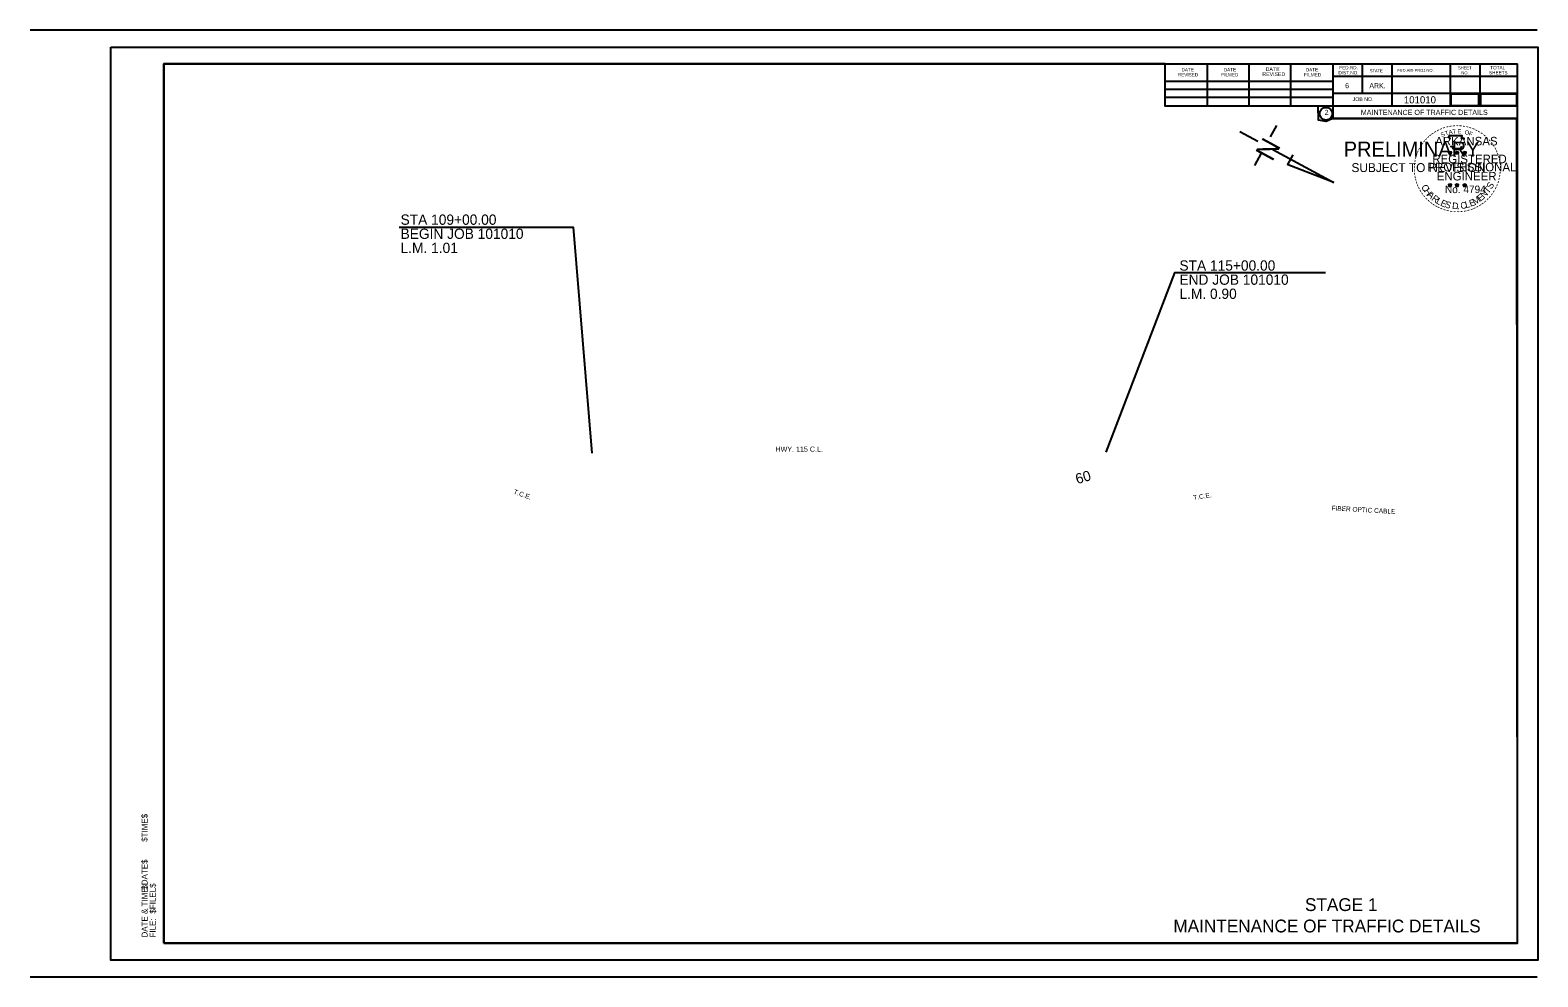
# Model space of a CAD drawing. Extents: x 6125 to 14104, y 8730 to 11067.
# Drawn here: x 9844 to 11605, y 9961 to 11067 of the extents above; entities that cross this region are included whole.
import ezdxf

# ---------------------------------------------------------------- set-up
doc = ezdxf.new("R2010")
doc.units = 0
for name, color, linetype in [('C-PSVP', 7, 'Continuous'), ('GREEN_TXT', 7, 'Continuous'), ('R_Border Notes', 7, 'Continuous'), ('R_MOT Stage 2', 7, 'Continuous'), ('R_Proposed Road', 7, 'Continuous'), ('R_Temp Const Easement Annot', 7, 'Continuous'), ('S_FIBER_OPTIC_CABLE_ANNOT', 7, 'Continuous'), ('SEAL-INFO', 7, 'Continuous'), ('SIGNATURE', 7, 'Continuous'), ('STA Text', 7, 'Continuous'), ('Stage 3', 7, 'Continuous'), ('TEXT', 7, 'Continuous')]:
    doc.layers.add(name, color=color, linetype=linetype)

msp = doc.modelspace()

# ---------------------------------------------------------------- linework, layer by layer
for p, q in [((11299.4, 10955.4), (11292, 10941.9)), ((11256.7, 10948.2), (11277.7, 10936.8)), ((11281.7, 10922.9), (11273.9, 10908.4)), ((11295.1, 10927.3), (11366.6, 10888.5)), ((11318.5, 10921), (11312.3, 10909.7)), ((11366.6, 10888.5), (11311.9, 10909.9))]:
    msp.add_line(p, q)
at = {"layer": 'C-PSVP'}
for p, q in [((11500.3, 10924), (11502.1, 10923.5)), ((11500.3, 10924), (11501.6, 10923.8)), ((11500.3, 10924), (11501.5, 10923.4)), ((11501, 10922), (11502.1, 10923.5)), ((11501, 10922), (11501.6, 10923.2)), ((11501, 10922), (11502, 10923.1)), ((11502.1, 10925.3), (11501.8, 10924.1)), ((11503.1, 10922), (11502, 10923.1)), ((11502.1, 10923.5), (11502.1, 10925.3)), ((11502.1, 10925.3), (11502.3, 10924.1)), ((11503.8, 10924), (11502.1, 10923.5)), ((11503.1, 10922), (11502.1, 10923.5)), ((11503.8, 10924), (11502.4, 10923.8)), ((11503.1, 10922), (11502.4, 10923.5)), ((11503.8, 10924), (11502.8, 10923.5)), ((11508.7, 10924), (11510.4, 10923.5)), ((11508.7, 10924), (11509.9, 10923.8)), ((11508.7, 10924), (11509.8, 10923.4)), ((11509.3, 10922), (11510.4, 10923.5)), ((11509.3, 10922), (11510, 10923.2)), ((11509.3, 10922), (11510.4, 10923.1)), ((11510.4, 10925.3), (11510.2, 10924.1)), ((11510.4, 10923.5), (11510.4, 10925.3)), ((11510.4, 10925.3), (11510.6, 10924.1)), ((11512.1, 10924), (11510.4, 10923.5)), ((11511.5, 10922), (11510.4, 10923.5)), ((11511.5, 10922), (11510.4, 10923.1)), ((11512.1, 10924), (11510.7, 10923.8)), ((11511.5, 10922), (11510.8, 10923.5)), ((11512.1, 10924), (11511.1, 10923.5)), ((11517.5, 10924), (11519.2, 10923.4)), ((11517.5, 10924), (11518.7, 10923.8)), ((11517.5, 10924), (11518.7, 10923.4)), ((11518.1, 10921.9), (11519.2, 10923.4)), ((11518.1, 10921.9), (11518.8, 10923.2)), ((11518.1, 10921.9), (11519.2, 10923)), ((11519.2, 10925.3), (11519, 10924)), ((11519.2, 10923.4), (11519.2, 10925.3)), ((11519.2, 10925.3), (11519.5, 10924)), ((11521, 10924), (11519.2, 10923.4)), ((11520.3, 10921.9), (11519.2, 10923.4)), ((11520.3, 10921.9), (11519.2, 10923)), ((11521, 10924), (11519.5, 10923.7)), ((11520.3, 10921.9), (11519.6, 10923.4)), ((11521, 10924), (11519.9, 10923.5)), ((11500.3, 10886.2), (11502, 10885.6)), ((11500.3, 10886.2), (11501.6, 10886)), ((11500.3, 10886.2), (11501.5, 10885.6)), ((11501, 10884.1), (11502, 10885.6)), ((11501, 10884.1), (11501.6, 10885.4)), ((11501, 10884.1), (11502, 10885.2)), ((11502, 10887.4), (11501.8, 10886.2)), ((11502, 10885.6), (11502, 10887.4)), ((11502, 10887.4), (11502.3, 10886.2)), ((11503.8, 10886.2), (11502, 10885.6)), ((11503.1, 10884.1), (11502, 10885.6)), ((11503.1, 10884.1), (11502, 10885.2)), ((11503.8, 10886.2), (11502.3, 10885.9)), ((11503.1, 10884.1), (11502.4, 10885.6)), ((11503.8, 10886.2), (11502.7, 10885.7)), ((11508.6, 10886.2), (11510.4, 10885.6)), ((11508.6, 10886.2), (11509.9, 10886)), ((11508.6, 10886.2), (11509.8, 10885.6)), ((11509.3, 10884.1), (11510.4, 10885.6)), ((11509.3, 10884.1), (11509.9, 10885.4)), ((11509.3, 10884.1), (11510.4, 10885.2)), ((11510.4, 10887.4), (11510.2, 10886.2)), ((11510.4, 10885.6), (11510.4, 10887.4)), ((11510.4, 10887.4), (11510.6, 10886.2)), ((11512.1, 10886.2), (11510.4, 10885.6)), ((11511.4, 10884.1), (11510.4, 10885.6)), ((11511.4, 10884.1), (11510.4, 10885.2)), ((11512.1, 10886.2), (11510.7, 10885.9)), ((11511.4, 10884.1), (11510.8, 10885.6)), ((11512.1, 10886.2), (11511.1, 10885.7)), ((11517.5, 10886.1), (11519.2, 10885.6)), ((11517.5, 10886.1), (11518.7, 10885.9)), ((11517.5, 10886.1), (11518.7, 10885.5)), ((11518.1, 10884.1), (11519.2, 10885.6)), ((11518.1, 10884.1), (11518.8, 10885.3)), ((11518.1, 10884.1), (11519.2, 10885.2)), ((11519.2, 10887.4), (11519, 10886.1)), ((11519.2, 10885.6), (11519.2, 10887.4)), ((11519.2, 10887.4), (11519.5, 10886.1)), ((11520.9, 10886.1), (11519.2, 10885.6)), ((11520.3, 10884.1), (11519.2, 10885.6)), ((11520.3, 10884.1), (11519.2, 10885.2)), ((11520.9, 10886.1), (11519.5, 10885.9)), ((11520.3, 10884.1), (11519.6, 10885.5)), ((11520.9, 10886.1), (11519.9, 10885.6))]:
    msp.add_line(p, q, dxfattribs=at)
for points in [[(11500.5, 10943.4), (11501.9, 10939.3)], [(11518.1, 10938.8), (11518.8, 10940.2), (11515.4, 10940.1), (11516.1, 10943.4), (11500.5, 10943.4)], [(11502.1, 10925.3), (11503.1, 10922), (11500.3, 10924), (11503.8, 10924), (11501, 10922), (11502.1, 10925.3)], [(11503, 10931.3), (11503, 10930.9), (11505.8, 10930.8), (11505.5, 10928.4), (11514.9, 10928.4), (11515.9, 10931.1)], [(11510.4, 10925.3), (11511.5, 10922), (11508.7, 10924), (11512.1, 10924), (11509.3, 10922), (11510.4, 10925.3)], [(11519.2, 10925.3), (11520.3, 10921.9), (11517.5, 10924), (11521, 10924), (11518.1, 10921.9), (11519.2, 10925.3)], [(11502, 10887.4), (11503.1, 10884.1), (11500.3, 10886.2), (11503.8, 10886.2), (11501, 10884.1), (11502, 10887.4)], [(11510.4, 10887.4), (11511.4, 10884.1), (11508.6, 10886.2), (11512.1, 10886.2), (11509.3, 10884.1), (11510.4, 10887.4)], [(11519.2, 10887.4), (11520.3, 10884.1), (11517.5, 10886.1), (11520.9, 10886.1), (11518.1, 10884.1), (11519.2, 10887.4)]]:
    msp.add_lwpolyline(points, dxfattribs=at)
for centre, radius in [((11502, 10923.5), 0.861), ((11502, 10923.5), 0.723), ((11502, 10923.5), 0.579), ((11502, 10923.5), 0.495), ((11502, 10923.5), 0.374), ((11502, 10923.5), 0.248), ((11502, 10923.5), 0.148), ((11510.4, 10923.5), 0.861), ((11510.4, 10923.5), 0.723), ((11510.4, 10923.5), 0.579), ((11510.4, 10923.5), 0.495), ((11510.4, 10923.5), 0.374), ((11510.4, 10923.5), 0.248), ((11510.4, 10923.5), 0.148), ((11519.2, 10923.4), 0.861), ((11519.2, 10923.4), 0.723), ((11519.2, 10923.4), 0.579), ((11519.2, 10923.4), 0.495), ((11519.2, 10923.4), 0.374), ((11519.2, 10923.4), 0.248), ((11519.2, 10923.4), 0.148), ((11502, 10885.6), 0.861), ((11502, 10885.6), 0.723), ((11502, 10885.6), 0.579), ((11502, 10885.6), 0.495), ((11502, 10885.6), 0.374), ((11502, 10885.6), 0.248), ((11502, 10885.6), 0.148), ((11510.4, 10885.6), 0.861), ((11510.4, 10885.6), 0.723), ((11510.4, 10885.6), 0.579), ((11510.4, 10885.6), 0.495), ((11510.4, 10885.6), 0.374), ((11510.4, 10885.6), 0.248), ((11510.4, 10885.6), 0.148), ((11519.2, 10885.6), 0.861), ((11519.2, 10885.6), 0.723), ((11519.2, 10885.6), 0.579), ((11519.2, 10885.6), 0.495), ((11519.2, 10885.6), 0.374), ((11519.2, 10885.6), 0.248), ((11519.2, 10885.6), 0.148)]:
    msp.add_circle(centre, radius, dxfattribs=at)
at = {"layer": 'GREEN_TXT'}
for p, q in [((11603.9, 11066.7), (9843.9, 11066.7)), ((10000, 11027.3), (11580.9, 11027.3)), ((10000, 10000), (10000, 11027.3)), ((10762.6, 11026), (10762.6, 11026)), ((10762.6, 11026), (10762.6, 11026)), ((11169.6, 10977.9), (11169.6, 11027.3)), ((11218.9, 10977.9), (11218.9, 11026.3)), ((11267.7, 10977.9), (11267.7, 11026.3)), ((11316.1, 10977.9), (11316.1, 11026.3)), ((11365.4, 11027.3), (11365.4, 10963.3)), ((11399.6, 11027.3), (11399.6, 10992.6)), ((11434.3, 11027.3), (11434.3, 10977.9)), ((11502.2, 11027.3), (11502.2, 10977.9)), ((11536.9, 11027.3), (11536.9, 10977.9)), ((11580.9, 10000), (11580.9, 11027.3)), ((11169.6, 11007.2), (11365.4, 11007.2)), ((11580.9, 11012.6), (11365.4, 11012.6)), ((11580.9, 11012.7), (11580.9, 11012.7)), ((11169.6, 10997.9), (11365.4, 10997.9)), ((11169.6, 10988.2), (11365.4, 10988.2)), ((11580.9, 10992.6), (11365.4, 10992.6)), ((11580.9, 10977.9), (11169.6, 10977.9)), ((11365.4, 10963.3), (11580.9, 10963.3)), ((11580.9, 10000), (10000, 10000)), ((9843.9, 9960.6), (11603.9, 9960.6))]:
    msp.add_line(p, q, dxfattribs=at)
msp.add_circle((11357.3, 10969), 7.33, dxfattribs=at)
at = {"layer": 'R_Proposed Road'}
msp.add_lwpolyline([(11503.2, 10978.6), (11535.9, 10978.6), (11535.9, 10991.9), (11503.2, 10991.9)], close=True, dxfattribs=at)
at = {"layer": 'SEAL-INFO'}
for points in [[(9938, 11046.8), (11604.7, 11046.8), (11604.7, 9980.1), (9938, 9980.1)], [(10000, 10000), (11580.9, 10000), (11580.3, 10963.3), (11365.4, 10963.3), (11357.3, 10959.9), (11348.5, 10961.4), (11348.3, 10977.9), (11169.6, 10977.9), (11169.6, 11027.3), (10000, 11027.3)]]:
    msp.add_lwpolyline(points, close=True, dxfattribs=at)
at = {"layer": 'STA Text'}
for points in [[(10274.9, 10836.4), (10478.1, 10836.4), (10500, 10572.5)], [(11356.6, 10783.3), (11180.4, 10783.3), (11100, 10573.8)]]:
    msp.add_lwpolyline(points, dxfattribs=at)
at = {"layer": 'Stage 3'}
msp.add_lwpolyline([(11537.7, 10978.6), (11580.1, 10978.6), (11580.1, 10991.9), (11537.7, 10991.9)], close=True, dxfattribs=at)

# ---------------------------------------------------------------- texts
for s, height, rotation, p in [('N', 23.3, 241.4896, (11284.6, 10943.1)), ('$TIME$', 6.98, 90, (9981, 10118.4)), ('$DATE$', 6.98, 90, (9981, 10062.5)), ('DATE & TIME:', 6.984, 90, (9981, 10006.6)), ('$FILEL$', 6.98, 90, (9990.6, 10034.5)), ('FILE: ', 6.98, 90, (9990.6, 10006.6))]:
    msp.add_text(s, height=height, rotation=rotation).set_placement(p)
at = {"layer": 'C-PSVP'}
for s, height, rotation, p in [('-', 8, 24.3072, (11491.1, 10947.7)), ('-', 8, 19.1761, (11494.3, 10949.1)), ('-', 8, 13.6302, (11498, 10950.3)), ('-', 8, 10.2193, (11501.4, 10951.1)), ('-', 8, 5.8968, (11505, 10951.6)), ('-', 8, 0.1862, (11508.9, 10952)), ('-', 8, 357.743, (11512.5, 10951.9)), ('-', 8, 352.1617, (11516.2, 10951.6)), ('-', 8, 347.2049, (11519.8, 10951.1)), ('-', 8, 342.3362, (11523, 10950.3)), ('-', 8, 337.8551, (11526.7, 10949.2)), ('-', 8, 54.2325, (11471.2, 10930.7)), ('-', 8, 50.6142, (11473.2, 10933.5)), ('-', 8, 48.4231, (11475.3, 10935.9)), ('-', 8, 42.9622, (11477.5, 10938.3)), ('-', 8, 38.9507, (11479.7, 10940.4)), ('-', 8, 36.2317, (11482, 10942.3)), ('-', 8, 34.0636, (11484.9, 10944.3)), ('-', 8, 28.7918, (11487.9, 10946.1)), ('S', 5, 21.594, (11492.3, 10941.8)), ('T', 5, 16.4036, (11496.9, 10943.5)), ('A', 5, 11.2132, (11501, 10944.7)), ('T', 5, 6.0228, (11505.2, 10945.6)), ('E', 5, 0.8323, (11510.8, 10946.1)), ('O', 5, 350.4515, (11518.8, 10945.1)), ('F', 5, 340.0707, (11523.5, 10943.9)), ('-', 8, 334.1211, (11529.8, 10947.8)), ('-', 8, 329.6409, (11532.7, 10946.4)), ('-', 8, 325.8627, (11535.9, 10944.6)), ('-', 8, 320.5297, (11539, 10942.5)), ('-', 8, 315.5786, (11542, 10940)), ('-', 8, 309.8797, (11544.8, 10937.3)), ('-', 8, 306.6522, (11547.5, 10934.3)), ('-', 8, 75.461, (11464.6, 10915.2)), ('-', 8, 72.3945, (11465.6, 10918.8)), ('-', 8, 67.7743, (11466.7, 10921.9)), ('-', 8, 62.8713, (11468, 10925)), ('-', 8, 58.0706, (11469.6, 10928)), ('-', 7, 303.6753, (11549.9, 10931.4)), ('-', 8, 299.6684, (11551.5, 10928.4)), ('-', 8, 294.6628, (11553.1, 10925.3)), ('-', 8, 290.5728, (11554.4, 10922.5)), ('-', 8, 285.1233, (11555.6, 10919.6)), ('-', 8, 89.0622, (11463.4, 10904.7)), ('-', 8, 94.1959, (11463.6, 10901.1)), ('-', 8, 98.9479, (11464, 10897.7)), ('-', 8, 85.1863, (11463.6, 10908.2)), ('-', 8, 81.2013, (11464, 10911.6)), ('-', 8, 280.5493, (11556.6, 10915.9)), ('-', 8, 276.5962, (11557.4, 10912)), ('-', 8, 263.5172, (11557.7, 10901.9)), ('-', 8, 274.3301, (11557.7, 10908.4)), ('-', 8, 269.9407, (11557.8, 10905.2)), ('-', 8, 101.7149, (11464.7, 10894.1)), ('-', 8, 105.4578, (11465.5, 10891.1)), ('-', 8, 109.0874, (11466.5, 10887.9)), ('-', 8, 114.0643, (11467.8, 10884.9)), ('-', 8, 115.7289, (11469.3, 10881.9)), ('C', 7.7, 296.9133, (11468.2, 10883.9)), ('H', 7.7, 303.2799, (11471.1, 10878.7)), ('T', 7.7, 51.5114, (11546.8, 10875.1)), ('S', 7.7, 57.878, (11550.5, 10880.3)), ('-', 8, 244.6197, (11553.5, 10885.1)), ('-', 8, 247.8887, (11554.8, 10888.3)), ('-', 8, 255.7626, (11555.9, 10891.8)), ('-', 8, 255.7626, (11556.8, 10895.3)), ('-', 8, 260.9953, (11557.4, 10898.6)), ('-', 8, 120.4471, (11471.1, 10878.9)), ('-', 8, 125.8934, (11473.1, 10876.1)), ('-', 8, 130.7181, (11475.4, 10873.4)), ('-', 8, 134.2238, (11478, 10870.6)), ('A', 7.7, 316.013, (11474.8, 10873.6)), ('-', 8, 138.9338, (11480.7, 10868.3)), ('-', 8, 144.6463, (11483.4, 10866.3)), ('R', 7.7, 322.3796, (11479.9, 10868.7)), ('L', 7.7, 328.7461, (11485, 10864.9)), ('E', 7.7, 335.1127, (11490.1, 10862.1)), ('S', 7.7, 341.4792, (11495.4, 10860)), ('D', 7.7, 354.2124, (11504.2, 10857.9)), ('C', 7.7, 6.9455, (11514.7, 10857.7)), ('L', 7.7, 13.3121, (11520.6, 10858.7)), ('E', 7.7, 19.6786, (11526.1, 10860.3)), ('M', 7.7, 32.4117, (11531.2, 10862.1)), ('E', 7.7, 38.7783, (11537.6, 10866.2)), ('N', 7.7, 45.1449, (11542, 10869.9)), ('-', 8, 215.7363, (11539.6, 10867.6)), ('-', 8, 221.0851, (11542.4, 10869.9)), ('-', 8, 225.7653, (11545, 10872.5)), ('-', 8, 231.2538, (11547.4, 10875.3)), ('-', 8, 233.8452, (11549.5, 10878.1)), ('-', 8, 239.0712, (11551.5, 10881.4)), ('-', 8, 148.0898, (11486.2, 10864.4)), ('-', 8, 151.5704, (11489.1, 10862.8)), ('-', 8, 154.6002, (11491.7, 10861.6)), ('-', 8, 158.5612, (11494.9, 10860.3)), ('-', 8, 162.7983, (11498.3, 10859.2)), ('-', 8, 167.5555, (11501.9, 10858.4)), ('-', 8, 173.1155, (11505.7, 10857.9)), ('-', 8, 176.5183, (11509.5, 10857.6)), ('-', 8, 181.5918, (11513.2, 10857.7)), ('.', 7.7, 0.5789, (11510.1, 10857.5)), ('-', 8, 185.8167, (11517.2, 10858.1)), ('-', 8, 191.2858, (11520.9, 10858.7)), ('-', 8, 195.4743, (11524.6, 10859.7)), ('-', 8, 200.7184, (11528, 10860.9)), ('-', 8, 204.2516, (11531, 10862.3)), ('-', 8, 207.3568, (11534.2, 10863.9)), ('-', 8, 212.2491, (11537, 10865.6))]:
    msp.add_text(s, height=height, rotation=rotation, dxfattribs=at).set_placement(p)
for s, height, p in [('ARKANSAS', 10, (11484.8, 10932)), ('REGISTERED', 10, (11481.4, 10911.2)), ('PROFESSIONAL', 10, (11475.6, 10901.7)), ('ENGINEER', 10, (11486.6, 10891.1)), ('No. 4794', 8.78, (11496.2, 10876.3))]:
    msp.add_text(s, height=height, dxfattribs=at).set_placement(p)
at = {"layer": 'GREEN_TXT'}
for s, height, p in [('DATE', 3.91, (11188.6, 11018.5)), ('DATE', 3.91, (11237.9, 11018.5)), ('DATE', 4.4, (11286.8, 11019)), ('DATE', 3.91, (11333.7, 11018.5)), ('FED.RD.', 3.91, (11372.8, 11020.9)), ('SHEET', 3.42, (11511.5, 11020.9)), ('TOTAL', 3.91, (11549.1, 11020.9)), ('REVISED', 3.91, (11184.2, 11012.6)), ('FILMED', 3.91, (11235, 11012.6)), ('REVISED', 4.4, (11282.9, 11013.1)), ('FILMED', 3.91, (11331.7, 11012.6)), ('DIST.NO.', 3.91, (11371.8, 11015)), ('6', 5.86, (11379.6, 10998.9)), ('STATE', 3.42, (11408.4, 11017.5)), ('FED.AID PROJ.NO.', 3.42, (11440.7, 11018)), ('NO.', 3.42, (11515.4, 11015)), ('SHEETS', 3.91, (11547.7, 11015)), ('JOB NO.', 4.4, (11388.4, 10983.8)), ('ARK.', 5.86, (11407.9, 10998.9)), ('2', 5.86, (11355.7, 10967.7)), ('STAGE 1', 15, (11332.7, 10037.5)), ('MAINTENANCE OF TRAFFIC DETAILS', 15, (11179, 10012.5))]:
    msp.add_text(s, height=height, dxfattribs=at).set_placement(p)
at = {"layer": 'R_Border Notes'}
for s, height, p in [('101010', 8.4, (11448.2, 10981.1)), ('MAINTENANCE OF TRAFFIC DETAILS', 6, (11397.9, 10967.6))]:
    msp.add_text(s, height=height, dxfattribs=at).set_placement(p)
at = {"layer": 'R_MOT Stage 2'}
msp.add_text('60', height=12, rotation=16.1937, dxfattribs=at).set_placement((11066.7, 10536.2))
at = {"layer": 'R_Temp Const Easement Annot'}
for rotation, p in [(340.4448, (10407.9, 10525.2)), (8.9375, (11202.7, 10517.6))]:
    msp.add_text('T.C.E.', height=5.5, rotation=rotation, dxfattribs=at).set_placement(p)
at = {"layer": 'S_FIBER_OPTIC_CABLE_ANNOT'}
msp.add_text('FIBER OPTIC CABLE', height=5.499, rotation=356.6986, dxfattribs=at).set_placement((11363.6, 10505.7))
at = {"layer": 'SIGNATURE'}
for s, height, p in [('PRELIMINARY', 17.5, (11377.9, 10919)), ('SUBJECT TO REVISION', 10.376, (11387, 10900.9))]:
    msp.add_text(s, height=height, dxfattribs=at).set_placement(p)
at = {"layer": 'STA Text'}
for s, p in [('STA 109+00.00', (10276.5, 10839.3)), ('BEGIN JOB 101010', (10276.5, 10822.8)), ('L.M. 1.01', (10276.5, 10806.3)), ('STA 115+00.00', (11186.1, 10785.7)), ('END JOB 101010', (11186.1, 10769.2)), ('L.M. 0.90', (11186.1, 10752.7))]:
    msp.add_text(s, height=12, dxfattribs=at).set_placement(p)
at = {"layer": 'TEXT'}
msp.add_text('HWY. 115 C.L.', height=6, rotation=0.0906, dxfattribs=at).set_placement((10714.4, 10574.1))

doc.saveas('drawing.dxf')
